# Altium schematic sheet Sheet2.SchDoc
size A4
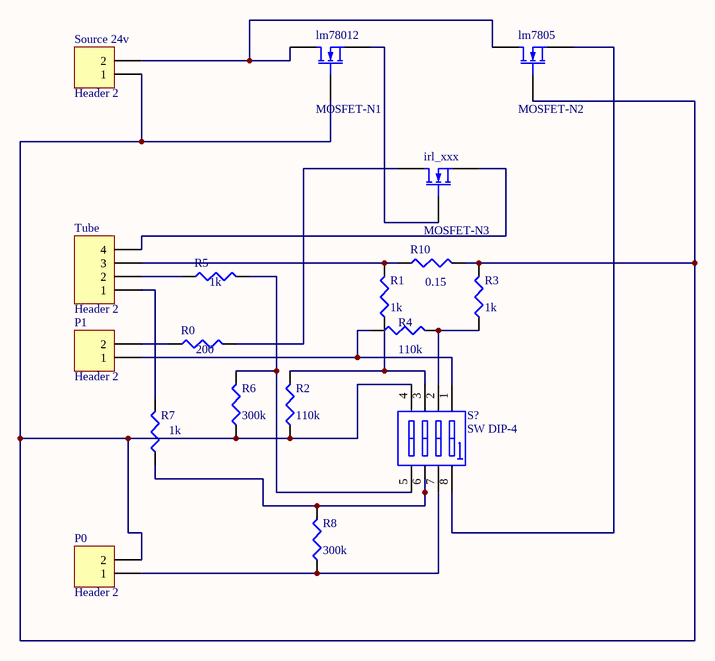
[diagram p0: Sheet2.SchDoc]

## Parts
irl_xxx  MOSFET-N3  [TO-220-AB]
lm7805  MOSFET-N2  [TO-220-AB]
lm78012  MOSFET-N1  [TO-220-AB]
P0  Header 2  [HDR1X2]
P1  Header 2  [HDR1X2]
R0  value 200  [J1-0603]  (hidden comment: Res3)
R1  value 1k  [J1-0603]  (hidden comment: Res3)
R2  value 110k  [J1-0603]  (hidden comment: Res3)
R3  value 1k  [J1-0603]  (hidden comment: Res3)
R4  value 110k  [J1-0603]  (hidden comment: Res3)
R5  value 1k  [J1-0603]  (hidden comment: Res3)
R6  value 300k  [J1-0603]  (hidden comment: Res3)
R7  value 1k  [J1-0603]  (hidden comment: Res3)
R8  value 300k  [J1-0603]  (hidden comment: Res3)
R10  value 0.15  [J1-0603]  (hidden comment: Res3)
S?  SW DIP-4  [SO8_M]
Source_24v  Header 2  [HDR1X2]
Tube  Header 2  [HDR1X4]

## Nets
Netirl_xxx_1: irl_xxx.1(D) R0.2
Netirl_xxx_2: irl_xxx.2(G) lm78012.3(S)
Netirl_xxx_3: irl_xxx.3(S) Tube.4
Netlm7805_1: lm7805.1(D) lm78012.1(D) Source_24v.2
Netlm7805_2: lm7805.2(G) lm78012.2(G) P0.2 R2.1 R3.2 R6.1 R10.2 S?.4(A4) Source_24v.1
Netlm7805_3: lm7805.3(S) S?.8(B1)
NetP0_1: P0.1 R8.1 S?.7(B2)
NetP1_1: P1.1 R4.1 S?.1(A1)
NetP1_2: P1.2 R0.1
NetR1_1: R1.1 R2.2 S?.3(A3)
NetR1_2: R1.2 R10.1 Tube.3
NetR3_1: R3.1 R4.2 S?.2(A2)
NetR5_1: R5.1 Tube.2
NetR5_2: R5.2 R6.2 S?.5(B4)
NetR7_1: R7.1 R8.2 S?.6(B3)
NetR7_2: R7.2 Tube.1

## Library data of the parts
irl_xxx lm7805 lm78012 = MOSFET-N: N-Channel MOSFET
P0 P1 Source_24v = Header 2: Header, 2-Pin
R0-R8 R10 = Res3: Resistor
S? = SW DIP-4: DIP Switch, 4 Position, SPST
Tube = Header 4: Header, 4-Pin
